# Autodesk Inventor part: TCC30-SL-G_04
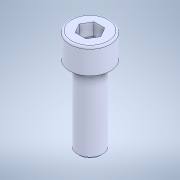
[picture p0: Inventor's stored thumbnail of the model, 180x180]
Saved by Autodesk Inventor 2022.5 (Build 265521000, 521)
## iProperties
Created: 2023-09
Part Number: TCC30-SL-G_04
Material: 一般
Document SubType Name: Modeling
Designer: ImaoCorp
Density: 1 g/cm^3
Appearance: 既定
Author: ImaoCorp
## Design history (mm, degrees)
feature "TCC30-SL-G_04"
node "ソリッド1"
